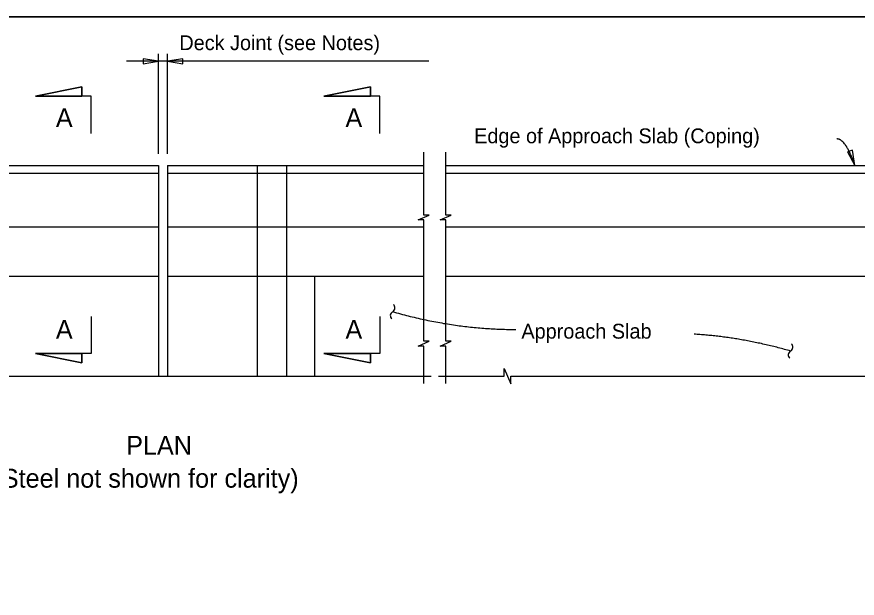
# Model space of a CAD drawing. Extents: x 0 to 41.1, y 0 to 25.9.
# Drawn here: x 18.01 to 29.43, y 18.05 to 25.95 of the extents above; entities that cross this region are included whole.
import ezdxf

# ---------------------------------------------------------------- set-up
doc = ezdxf.new("R2010")
doc.units = 0
for name, color, linetype in [('ActivePts-ConstElements', 7, 'Continuous'), ('Dimension', 7, 'Continuous'), ('Miscellaneous1', 7, 'Continuous'), ('TextStructures', 7, 'Continuous'), ('TrafBarrierConc', 7, 'Continuous')]:
    doc.layers.add(name, color=color, linetype=linetype)

msp = doc.modelspace()

# ---------------------------------------------------------------- linework, layer by layer
at = {"layer": 'ActivePts-ConstElements'}
msp.add_lwpolyline([(0, 0), (41.051, 0), (41.051, 25.946), (0, 25.946)], close=True, dxfattribs=at)
at = {"layer": 'Dimension'}
for p, q in [((19.93, 24.083), (19.93, 25.443)), ((20.053, 24.083), (20.053, 25.443)), ((23.605, 25.342), (19.499, 25.342)), ((18.258, 24.868), (18.89, 24.995)), ((18.89, 24.995), (18.89, 24.868)), ((22.179, 24.868), (22.812, 24.995)), ((22.812, 24.995), (22.812, 24.868)), ((19.017, 24.868), (18.258, 24.868)), ((19.017, 24.362), (19.017, 24.868)), ((22.939, 24.868), (22.179, 24.868)), ((22.939, 24.362), (22.939, 24.868)), ((19.017, 21.876), (19.017, 21.369)), ((22.939, 21.876), (22.939, 21.369)), ((19.017, 21.369), (18.258, 21.369)), ((18.258, 21.369), (18.89, 21.243)), ((18.89, 21.243), (18.89, 21.369)), ((22.939, 21.369), (22.179, 21.369)), ((22.179, 21.369), (22.812, 21.243)), ((22.812, 21.243), (22.812, 21.369))]:
    msp.add_line(p, q, dxfattribs=at)
for points in [[(19.93, 25.342), (19.722, 25.377), (19.722, 25.306)], [(20.053, 25.342), (20.261, 25.306), (20.261, 25.377)], [(18.89, 24.868), (18.89, 24.995), (18.258, 24.868)], [(22.812, 24.868), (22.812, 24.995), (22.179, 24.868)], [(29.395, 23.924), (29.361, 24.132), (29.295, 24.11)], [(18.89, 21.369), (18.89, 21.243), (18.258, 21.369)], [(22.812, 21.369), (22.812, 21.243), (22.179, 21.369)]]:
    msp.add_lwpolyline(points, close=True, dxfattribs=at)
for points in [[(23.537, 22.14), (23.537, 23.186), (23.46, 23.186), (23.61, 23.252), (23.537, 23.252), (23.537, 24.107)], [(23.837, 22.14), (23.837, 23.186), (23.76, 23.186), (23.91, 23.252), (23.837, 23.252), (23.837, 24.107)], [(23.537, 20.963), (23.537, 21.472), (23.46, 21.472), (23.61, 21.539), (23.537, 21.539), (23.537, 22.14)], [(23.837, 20.963), (23.837, 21.472), (23.76, 21.472), (23.91, 21.539), (23.837, 21.539), (23.837, 22.14)], [(11.857, 21.063), (14.406, 21.063), (14.406, 21.167), (14.451, 21.063), (14.496, 20.96), (14.496, 21.063), (19.93, 21.063)], [(23.737, 21.063), (24.629, 21.063), (24.629, 21.167), (24.674, 21.063), (24.719, 20.96), (24.719, 21.063), (30.61, 21.063)], [(19.93, 21.063), (23.637, 21.063)]]:
    msp.add_lwpolyline(points, dxfattribs=at)
for centre, start, end in [((23.141, 21.886), 118.0989, 229.8261), ((23.085, 21.992), 298.0989, 49.8261), ((28.493, 21.458), 298.0989, 49.8261), ((28.549, 21.352), 118.0989, 229.8261)]:
    msp.add_arc(centre, 0.0596, start, end, dxfattribs=at)
for points in [[(29.395, 23.924), (29.272, 24.287), (29.149, 24.287)], [(23.113, 21.94), (23.95, 21.698), (24.788, 21.698)], [(28.521, 21.404), (27.865, 21.593), (27.209, 21.634)]]:
    msp.add_open_spline(points, degree=2, dxfattribs=at)
at = {"layer": 'Miscellaneous1'}
msp.add_lwpolyline([(0, 25.946), (41.051, 25.946), (41.051, 0), (0, 0)], close=True, dxfattribs=at)
at = {"layer": 'TrafBarrierConc'}
for p, q in [((11.931, 23.924), (19.93, 23.924)), ((19.93, 23.924), (19.93, 21.063)), ((20.053, 23.924), (20.053, 21.063)), ((20.053, 23.924), (23.537, 23.924)), ((21.273, 23.924), (21.273, 21.063)), ((21.67, 23.924), (21.67, 21.063)), ((23.837, 23.924), (39.818, 23.924)), ((11.931, 23.82), (19.93, 23.82)), ((20.053, 23.82), (23.537, 23.82)), ((23.837, 23.82), (33.151, 23.82)), ((11.931, 23.091), (19.93, 23.091)), ((20.053, 23.091), (23.537, 23.091)), ((23.837, 23.091), (33.151, 23.091)), ((11.931, 22.424), (19.93, 22.424)), ((20.053, 22.424), (23.537, 22.424)), ((22.053, 22.424), (22.053, 21.063)), ((23.837, 22.424), (36.818, 22.424))]:
    msp.add_line(p, q, dxfattribs=at)

# ---------------------------------------------------------------- texts
at = {"layer": 'Dimension'}
for s, p in [('PLAN', (19.492, 19.996)), ('(Reinforcing Steel not shown for clarity)', (15.862, 19.548))]:
    msp.add_text(s, height=0.256, dxfattribs=at).set_placement(p)
at = {"layer": 'TextStructures'}
for s, height, p in [('Deck Joint (see Notes)', 0.2016, (20.215, 25.493)), ('A', 0.256, (18.537, 24.447)), ('A', 0.256, (22.472, 24.447)), ('Edge of Approach Slab (Coping)', 0.2016, (24.221, 24.228)), ('A', 0.256, (18.537, 21.571)), ('A', 0.256, (22.472, 21.571)), ('Approach Slab', 0.2016, (24.863, 21.573))]:
    msp.add_text(s, height=height, dxfattribs=at).set_placement(p)

doc.saveas('drawing.dxf')
